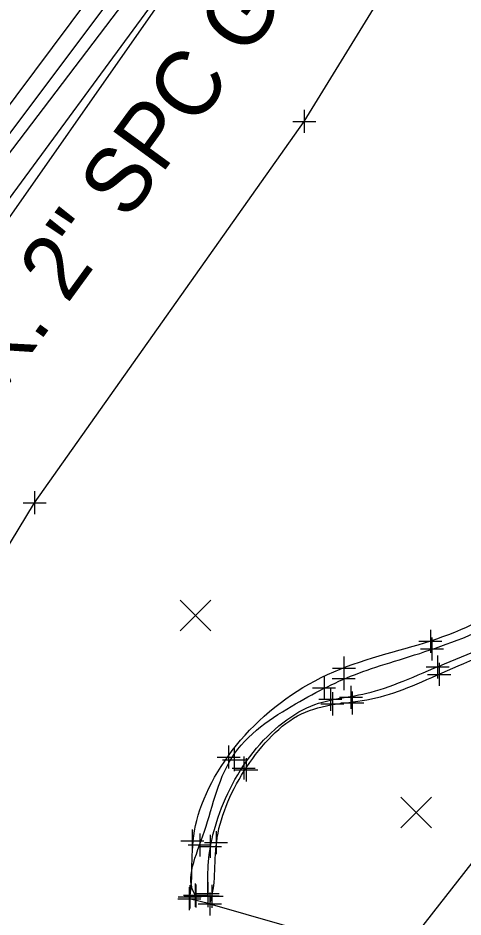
# Model space of a CAD drawing. Extents: x 1324089 to 1329959, y 459099 to 462017.
# Drawn here: x 1325849.08 to 1325868.39, y 460966.51 to 461005.53 of the extents above; entities that cross this region are included whole.
import ezdxf

# ---------------------------------------------------------------- set-up
doc = ezdxf.new("R2010")
doc.units = 0
for name, color, linetype in [('DR_X_Ditch', 7, 'Continuous'), ('PM_X_Edge_Line', 7, 'Continuous'), ('PM_X_Surveyed_Line', 7, 'Continuous'), ('PV_X_EOP', 7, 'Continuous'), ('RD_X_Wall', 7, 'Continuous'), ('RW_X_Fee_RW', 7, 'Continuous'), ('SV_X_Break_Lines', 7, 'Continuous'), ('SV_X_Random_Point', 7, 'Continuous'), ('SV_X_Shot_Marker', 7, 'Continuous'), ('UT_X_Gas', 7, 'Continuous'), ('UT_X_Gas_Text', 7, 'Continuous'), ('VG_X_Flower_Bed', 7, 'Continuous')]:
    doc.layers.add(name, color=color, linetype=linetype)

msp = doc.modelspace()

# ---------------------------------------------------------------- linework, layer by layer
at = {"layer": 'DR_X_Ditch'}
msp.add_lwpolyline([(1325831.73, 460955.594), (1325839.04, 460966.713), (1325849.802, 460984.492), (1325861.505, 461001.047), (1325868.258, 461012.033)], dxfattribs=at)
at = {"layer": 'PM_X_Edge_Line'}
msp.add_line((1325840.724, 460991.067), (1325861.637, 461019.052), dxfattribs=at)
at = {"layer": 'PM_X_Surveyed_Line'}
msp.add_lwpolyline([(1325496.021, 460524.258), (1325516.969, 460552.292), (1325536.736, 460578.687), (1325557.068, 460606.109), (1325577.394, 460633.551), (1325597.522, 460661.262), (1325617.796, 460689.111), (1325638.482, 460716.728), (1325658.706, 460744.046), (1325678.833, 460771.458), (1325699.002, 460798.955), (1325719.69, 460827.079), (1325740.268, 460854.833), (1325759.305, 460880.538), (1325780.721, 460909.395), (1325799.76, 460935.261), (1325820.517, 460963.727), (1325840.724, 460991.067), (1325861.637, 461019.052), (1325881.763, 461046.305), (1325900.523, 461071.568)], dxfattribs=at)
at = {"layer": 'PV_X_EOP'}
msp.add_lwpolyline([(1325599.889, 460659.68), (1325606.14, 460668.128), (1325605.325, 460670.668), (1325618.613, 460688.48), (1325639.213, 460716.237), (1325659.298, 460743.539), (1325679.42, 460770.952), (1325699.674, 460798.434), (1325720.276, 460826.771), (1325740.704, 460854.481), (1325759.656, 460880.399), (1325781.001, 460909.088), (1325800.154, 460934.895), (1325820.976, 460963.358), (1325841.646, 460990.376), (1325860.103, 461014.662), (1325864.144, 461018.087), (1325883.164, 461043.301), (1325885.354, 461048.429), (1325901.488, 461070.932), (1325836.638, 460984.425)], dxfattribs=at)
at = {"layer": 'RD_X_Wall'}
for p, q in [((1325856.796, 460967.418), (1325856.771, 460967.456)), ((1325856.796, 460967.418), (1325857.318, 460967.428)), ((1325857.318, 460967.428), (1325857.317, 460967.525))]:
    msp.add_line(p, q, dxfattribs=at)
for points in [[(1325856.771, 460967.456), (1325856.313, 460968.172), (1325857.296, 460970.074), (1325858.037, 460973.896), (1325861.484, 460976.019), (1325863.865, 460977.204), (1325867.336, 460978.131), (1325871.375, 460979.836), (1325873.339, 460984.04), (1325873.656, 460988.079), (1325874.469, 460992.019), (1325876.009, 460995.895), (1325879.385, 460998.633), (1325882.83, 461000.216), (1325884.283, 461000.554), (1325884.543, 461000.603)], [(1325857.317, 460967.525), (1325857.308, 460968.344), (1325857.299, 460969.867), (1325858.758, 460973.436), (1325861.66, 460976.022), (1325864.281, 460976.001), (1325867.669, 460977.605), (1325872.032, 460979.173), (1325874.146, 460983.781), (1325874.55, 460987.917), (1325875.162, 460991.8), (1325876.879, 460995.362), (1325879.914, 460997.778), (1325883.558, 460999.38), (1325884.382, 460999.521), (1325884.688, 460999.576)]]:
    msp.add_open_spline(points, degree=3, dxfattribs=at)
at = {"layer": 'RW_X_Fee_RW'}
msp.add_line((1325947.564, 461069.638), (1325722.652, 460781.993), dxfattribs=at)
at = {"layer": 'SV_X_Break_Lines'}
for p, q in [((1325856.517, 460967.298), (1325856.535, 460967.383)), ((1325857.407, 460967.074), (1325856.517, 460967.298)), ((1325857.407, 460967.074), (1325857.491, 460967.405))]:
    msp.add_line(p, q, dxfattribs=at)
msp.add_lwpolyline([(1325822.57, 460962.088), (1325843.23, 460989.064), (1325859.401, 461012.171), (1325866.444, 461017.707)], dxfattribs=at)
for points in [[(1325856.535, 460967.383), (1325856.712, 460968.188), (1325856.354, 460970.351), (1325858.435, 460974.341), (1325862.368, 460977.374), (1325867.144, 460978.36), (1325870.999, 460980.181), (1325873.101, 460984.078), (1325873.267, 460988.178), (1325874.07, 460992.185), (1325875.886, 460995.988), (1325879.321, 460998.959), (1325882.577, 461000.394), (1325884.43, 461000.772), (1325884.681, 461000.816)], [(1325857.491, 460967.405), (1325857.691, 460968.193), (1325857.444, 460970.085), (1325858.993, 460973.337), (1325861.423, 460975.834), (1325864.637, 460975.749), (1325867.698, 460977.267), (1325872.246, 460979.025), (1325874.342, 460983.724), (1325874.707, 460987.95), (1325875.506, 460991.722), (1325876.97, 460995.321), (1325880.518, 460997.391), (1325882.441, 460999.749), (1325884.861, 460999.199), (1325884.924, 460999.461)]]:
    msp.add_open_spline(points, degree=3, dxfattribs=at)
at = {"layer": 'SV_X_Random_Point'}
for p, q in [((1325856.114, 460978.932), (1325857.447, 460980.267)), ((1325856.114, 460980.267), (1325857.447, 460978.932)), ((1325865.697, 460970.374), (1325867.03, 460971.709)), ((1325865.697, 460971.709), (1325867.03, 460970.374))]:
    msp.add_line(p, q, dxfattribs=at)
at = {"layer": 'SV_X_Shot_Marker'}
for p, q in [((1325861.505, 461001.547), (1325861.505, 461000.547)), ((1325861.005, 461001.047), (1325862.005, 461001.047)), ((1325861.505, 461001.047), (1325861.505, 461001.047)), ((1325849.802, 460984.992), (1325849.802, 460983.992)), ((1325849.302, 460984.492), (1325850.302, 460984.492)), ((1325849.802, 460984.492), (1325849.802, 460984.492)), ((1325866.978, 460978.981), (1325866.978, 460977.981)), ((1325867.045, 460978.645), (1325867.045, 460977.645)), ((1325866.478, 460978.481), (1325867.478, 460978.481)), ((1325866.978, 460978.481), (1325866.978, 460978.481)), ((1325863.222, 460977.814), (1325863.222, 460976.814)), ((1325866.545, 460978.145), (1325867.545, 460978.145)), ((1325867.045, 460978.145), (1325867.045, 460978.145)), ((1325867.291, 460977.862), (1325867.291, 460976.862)), ((1325867.356, 460977.536), (1325867.356, 460976.536)), ((1325862.722, 460977.314), (1325863.722, 460977.314)), ((1325863.215, 460977.36), (1325863.215, 460976.36)), ((1325863.222, 460977.314), (1325863.222, 460977.314)), ((1325866.791, 460977.362), (1325867.791, 460977.362)), ((1325866.856, 460977.036), (1325867.856, 460977.036)), ((1325867.291, 460977.362), (1325867.291, 460977.362)), ((1325867.356, 460977.036), (1325867.356, 460977.036)), ((1325862.365, 460976.949), (1325862.365, 460975.949)), ((1325862.715, 460976.86), (1325863.715, 460976.86)), ((1325863.215, 460976.86), (1325863.215, 460976.86)), ((1325861.865, 460976.449), (1325862.865, 460976.449)), ((1325862.365, 460976.449), (1325862.365, 460976.449)), ((1325862.636, 460976.459), (1325862.636, 460975.459)), ((1325862.726, 460976.261), (1325862.726, 460975.261)), ((1325863.529, 460976.545), (1325863.529, 460975.545)), ((1325863.587, 460976.302), (1325863.587, 460975.302)), ((1325862.136, 460975.959), (1325863.136, 460975.959)), ((1325862.636, 460975.959), (1325862.636, 460975.959)), ((1325863.029, 460976.045), (1325864.029, 460976.045)), ((1325863.529, 460976.045), (1325863.529, 460976.045)), ((1325862.226, 460975.761), (1325863.226, 460975.761)), ((1325862.726, 460975.761), (1325862.726, 460975.761)), ((1325863.087, 460975.802), (1325864.087, 460975.802)), ((1325863.587, 460975.802), (1325863.587, 460975.802)), ((1325858.221, 460973.947), (1325858.221, 460972.947)), ((1325858.458, 460973.834), (1325858.458, 460972.834)), ((1325857.721, 460973.447), (1325858.721, 460973.447)), ((1325857.958, 460973.334), (1325858.958, 460973.334)), ((1325858.221, 460973.447), (1325858.221, 460973.447)), ((1325858.458, 460973.334), (1325858.458, 460973.334)), ((1325858.88, 460973.474), (1325858.88, 460972.474)), ((1325858.983, 460973.397), (1325858.983, 460972.397)), ((1325858.38, 460972.974), (1325859.38, 460972.974)), ((1325858.483, 460972.897), (1325859.483, 460972.897)), ((1325858.88, 460972.974), (1325858.88, 460972.974)), ((1325858.983, 460972.897), (1325858.983, 460972.897)), ((1325856.643, 460970.307), (1325856.643, 460969.307)), ((1325856.972, 460970.136), (1325856.972, 460969.136)), ((1325857.42, 460970.07), (1325857.42, 460969.07)), ((1325857.675, 460970.238), (1325857.675, 460969.238)), ((1325856.143, 460969.807), (1325857.143, 460969.807)), ((1325856.472, 460969.636), (1325857.472, 460969.636)), ((1325856.643, 460969.807), (1325856.643, 460969.807)), ((1325856.972, 460969.636), (1325856.972, 460969.636)), ((1325857.175, 460969.738), (1325858.175, 460969.738)), ((1325857.675, 460969.738), (1325857.675, 460969.738)), ((1325856.92, 460969.57), (1325857.92, 460969.57)), ((1325857.42, 460969.57), (1325857.42, 460969.57)), ((1325856.517, 460967.798), (1325856.517, 460966.798)), ((1325856.535, 460967.883), (1325856.535, 460966.883)), ((1325856.771, 460967.956), (1325856.771, 460966.956)), ((1325856.796, 460967.918), (1325856.796, 460966.918)), ((1325856.796, 460967.918), (1325856.796, 460966.918)), ((1325857.317, 460968.025), (1325857.317, 460967.025)), ((1325857.318, 460967.928), (1325857.318, 460966.928)), ((1325857.491, 460967.905), (1325857.491, 460966.905)), ((1325856.017, 460967.298), (1325857.017, 460967.298)), ((1325856.035, 460967.383), (1325857.035, 460967.383)), ((1325856.271, 460967.456), (1325857.271, 460967.456)), ((1325856.296, 460967.418), (1325857.296, 460967.418)), ((1325856.296, 460967.418), (1325857.296, 460967.418)), ((1325856.517, 460967.298), (1325856.517, 460967.298)), ((1325856.535, 460967.383), (1325856.535, 460967.383)), ((1325856.771, 460967.456), (1325856.771, 460967.456)), ((1325856.796, 460967.418), (1325856.796, 460967.418)), ((1325856.796, 460967.418), (1325856.796, 460967.418)), ((1325856.817, 460967.525), (1325857.817, 460967.525)), ((1325856.818, 460967.428), (1325857.818, 460967.428)), ((1325856.991, 460967.405), (1325857.991, 460967.405)), ((1325857.317, 460967.525), (1325857.317, 460967.525)), ((1325857.318, 460967.428), (1325857.318, 460967.428)), ((1325857.407, 460967.574), (1325857.407, 460966.574)), ((1325857.407, 460967.574), (1325857.407, 460966.574)), ((1325857.407, 460967.574), (1325857.407, 460966.574)), ((1325857.491, 460967.405), (1325857.491, 460967.405)), ((1325856.907, 460967.074), (1325857.907, 460967.074)), ((1325856.907, 460967.074), (1325857.907, 460967.074)), ((1325856.907, 460967.074), (1325857.907, 460967.074)), ((1325857.407, 460967.074), (1325857.407, 460967.074)), ((1325857.407, 460967.074), (1325857.407, 460967.074)), ((1325857.407, 460967.074), (1325857.407, 460967.074))]:
    msp.add_line(p, q, dxfattribs=at)
at = {"layer": 'UT_X_Gas'}
msp.add_line((1325756.111, 460871.47), (1326071.476, 461301.361), dxfattribs=at)
at = {"layer": 'VG_X_Flower_Bed'}
msp.add_lwpolyline([(1325857.407, 460967.074), (1325869.9, 460963.493), (1325870.093, 460959.847), (1325868.726, 460955.669), (1325869.812, 460952.46), (1325872.863, 460950.679), (1325875.419, 460950.562), (1325876.279, 460951.555)], dxfattribs=at)

# ---------------------------------------------------------------- texts
at = {"layer": 'UT_X_Gas_Text'}
msp.add_text('EX. 2" SPC G.M.', height=2.8, rotation=53.9419, dxfattribs=at).set_placement((1325847.051, 460987.37))

doc.saveas('drawing.dxf')
